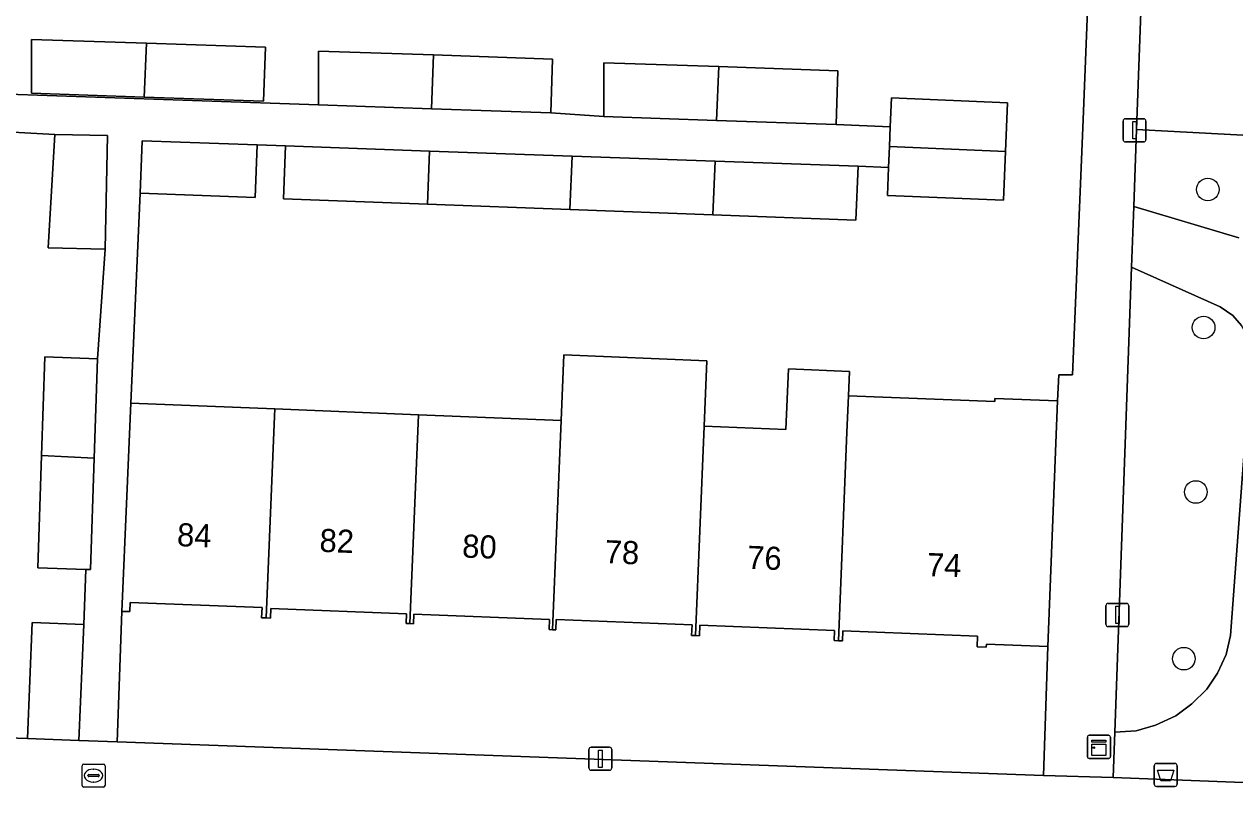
# Model space of a CAD drawing. Extents: x 161354 to 162026, y 386504 to 387460.
# Drawn here: x 161825.7 to 161878.1, y 386751.9 to 386785.2 of the extents above; entities that cross this region are included whole.
import ezdxf

# ---------------------------------------------------------------- set-up
doc = ezdxf.new("R2010")
doc.units = 0
for name, color, linetype in [('IMGEO_Afvalbak', 7, 'Continuous'), ('IMGEO_Boom', 7, 'Continuous'), ('IMGEO_Erf', 7, 'Continuous'), ('IMGEO_Groenvoorziening', 7, 'Continuous'), ('IMGEO_Kast', 7, 'Continuous'), ('IMGEO_Kolk', 7, 'Continuous'), ('IMGEO_Lichtmast', 7, 'Continuous'), ('IMGEO_Pand', 7, 'Continuous'), ('IMGEO_Pand_nummerreeks', 7, 'Continuous'), ('IMGEO_Voetpad_gesloten', 7, 'Continuous'), ('IMGEO_Voetpad_open', 7, 'Continuous')]:
    doc.layers.add(name, color=color, linetype=linetype)

msp = doc.modelspace()

# ---------------------------------------------------------------- linework, layer by layer
at = {"layer": 'IMGEO_Afvalbak'}
for p, q in [((161874.64, 386752.314), (161874.64, 386753.114)), ((161874.64, 386753.114), (161874.64, 386752.314)), ((161874.74, 386753.214), (161875.53, 386753.214)), ((161875.53, 386753.214), (161874.74, 386753.214)), ((161875.63, 386753.114), (161875.63, 386752.314)), ((161875.63, 386752.314), (161875.63, 386753.114)), ((161875.53, 386752.214), (161874.74, 386752.214)), ((161874.74, 386752.214), (161875.53, 386752.214))]:
    msp.add_line(p, q, dxfattribs=at)
msp.add_lwpolyline([(161874.783, 386752.928), (161875.487, 386752.928), (161875.338, 386752.458), (161874.932, 386752.458), (161874.783, 386752.928)], dxfattribs=at)
for centre, start, end in [((161874.74, 386753.114), 90, 180), ((161874.74, 386753.114), 90, 180), ((161875.53, 386753.114), 0, 90), ((161875.53, 386753.114), 360, 90), ((161874.74, 386752.314), 180, 270), ((161874.74, 386752.314), 180, 270), ((161875.53, 386752.314), 270, 0), ((161875.53, 386752.314), 270, 0)]:
    msp.add_arc(centre, 0.1, start, end, dxfattribs=at)
at = {"layer": 'IMGEO_Boom'}
for centre in [(161876.96, 386778.067), (161876.778, 386772.088), (161876.443, 386764.968), (161875.917, 386757.749)]:
    msp.add_circle(centre, 0.489, dxfattribs=at)
at = {"layer": 'IMGEO_Erf'}
for points in [[(161879.556, 386799.87), (161874.587, 386800.222), (161873.877, 386780.663), (161923.762, 386778.004)], [(161823.329, 386782.256), (161838.45, 386781.728), (161838.45, 386784.059), (161843.436, 386783.89), (161848.583, 386783.716), (161848.504, 386781.388), (161850.807, 386781.223), (161850.807, 386783.554), (161855.786, 386783.386), (161860.94, 386783.211), (161860.861, 386780.883), (161863.209, 386780.776), (161863.263, 386782.037), (161868.288, 386781.823), (161868.198, 386779.708), (161868.108, 386777.597), (161863.083, 386777.811), (161863.134, 386779.012), (161861.817, 386779.071), (161861.714, 386776.736), (161855.525, 386776.969), (161849.334, 386777.202), (161843.163, 386777.434), (161836.927, 386777.668), (161837.021, 386779.952), (161835.792, 386779.996), (161835.711, 386777.714), (161830.726, 386777.902), (161830.322, 386768.815), (161836.553, 386768.564), (161842.777, 386768.313), (161848.958, 386768.064), (161849.073, 386770.901), (161855.271, 386770.644), (161855.154, 386767.814), (161858.692, 386767.671), (161858.801, 386770.299), (161861.444, 386770.19), (161861.4, 386769.136), (161867.734, 386768.886), (161867.74, 386769.022), (161870.449, 386768.915), (161870.503, 386770.041), (161871.106, 386770.041), (161871.542, 386780.734), (161871.928, 386790.211)]]:
    msp.add_lwpolyline(points, dxfattribs=at)
for points in [[(161836.148, 386784.225), (161836.069, 386781.897), (161830.905, 386782.071), (161826.015, 386782.237), (161826.015, 386784.568), (161831.006, 386784.399)], [(161826.454, 386766.547), (161826.594, 386770.813), (161828.875, 386770.738), (161829.214, 386775.488), (161826.737, 386775.537), (161827.029, 386780.443), (161818.183, 386780.932), (161818.138, 386779.724), (161818.317, 386779.717), (161818.073, 386773.284), (161819.671, 386773.197), (161819.434, 386766.94), (161817.834, 386766.996), (161817.607, 386761.012), (161817.399, 386761.029), (161817.391, 386760.883), (161820.524, 386760.72), (161820.199, 386754.483), (161825.842, 386754.299), (161826.048, 386759.315), (161828.283, 386759.223), (161828.369, 386761.615), (161826.294, 386761.683)], [(161870.028, 386758.279), (161867.373, 386758.384), (161867.367, 386758.244), (161866.967, 386758.26), (161866.985, 386758.722), (161861.159, 386758.953), (161861.142, 386758.516), (161860.96, 386758.523), (161860.782, 386758.53), (161860.799, 386758.969), (161854.969, 386759.2), (161854.951, 386758.739), (161854.778, 386758.746), (161854.606, 386758.752), (161854.624, 386759.215), (161848.748, 386759.448), (161848.73, 386758.996), (161848.582, 386759.002), (161848.435, 386759.008), (161848.453, 386759.448), (161842.581, 386759.68), (161842.564, 386759.263), (161842.402, 386759.269), (161842.239, 386759.276), (161842.255, 386759.69), (161836.389, 386759.922), (161836.372, 386759.509), (161836.178, 386759.517), (161835.987, 386759.524), (161836.004, 386759.959), (161830.296, 386760.185), (161830.28, 386759.789), (161829.933, 386759.795), (161829.735, 386754.147), (161869.843, 386752.696)]]:
    msp.add_lwpolyline(points, close=True, dxfattribs=at)
at = {"layer": 'IMGEO_Groenvoorziening'}
for points in [[(161923.762, 386778.004), (161873.877, 386780.663), (161873.757, 386777.335), (161878.306, 386775.969)], [(161878.306, 386775.969), (161873.757, 386777.335), (161873.662, 386774.698), (161877.497, 386772.981), (161878.041, 386772.614), (161878.419, 386772.175)], [(161878.846, 386770.985), (161877.946, 386758.754), (161877.758, 386757.934), (161877.38, 386757.124), (161876.921, 386756.422), (161876.274, 386755.788), (161875.572, 386755.274), (161874.695, 386754.87), (161873.858, 386754.626), (161872.933, 386754.57), (161872.862, 386752.607), (161878.487, 386752.39)]]:
    msp.add_lwpolyline(points, dxfattribs=at)
msp.add_lwpolyline([(161872.933, 386754.57), (161873.858, 386754.626), (161874.695, 386754.87), (161875.572, 386755.274), (161876.274, 386755.788), (161876.921, 386756.422), (161877.38, 386757.124), (161877.758, 386757.934), (161877.946, 386758.754), (161878.846, 386770.985), (161878.729, 386771.595), (161878.419, 386772.175), (161878.041, 386772.614), (161877.497, 386772.981), (161873.662, 386774.698)], close=True, dxfattribs=at)
at = {"layer": 'IMGEO_Kast'}
for p, q in [((161871.743, 386753.505), (161871.743, 386754.346)), ((161871.743, 386754.346), (161871.743, 386753.505)), ((161871.818, 386754.43), (161872.659, 386754.43)), ((161872.659, 386754.43), (161871.818, 386754.43)), ((161872.743, 386754.355), (161872.743, 386753.514)), ((161872.743, 386753.514), (161872.743, 386754.355)), ((161872.668, 386753.43), (161871.827, 386753.43)), ((161871.827, 386753.43), (161872.668, 386753.43))]:
    msp.add_line(p, q, dxfattribs=at)
for points in [[(161871.938, 386754.22), (161872.538, 386754.22), (161872.538, 386754.135), (161871.938, 386754.135), (161871.938, 386754.22)], [(161871.938, 386754.045), (161872.538, 386754.045), (161872.538, 386753.556), (161871.938, 386753.556), (161871.938, 386754.045)]]:
    msp.add_lwpolyline(points, dxfattribs=at)
msp.add_circle((161872.022, 386753.894), 0.0377, dxfattribs=at)
for centre, start, end in [((161871.821, 386754.352), 92.4484, 184.2845), ((161871.821, 386754.352), 92.4484, 184.2845), ((161872.665, 386754.352), 2.4484, 94.2845), ((161872.665, 386754.352), 2.4484, 94.2845), ((161871.821, 386753.508), 182.4484, 274.2845), ((161871.821, 386753.508), 182.4484, 274.2845), ((161872.665, 386753.508), 272.4484, 4.2845), ((161872.665, 386753.508), 272.4484, 4.2845)]:
    msp.add_arc(centre, 0.0779, start, end, dxfattribs=at)
at = {"layer": 'IMGEO_Kolk'}
for p, q in [((161828.209, 386752.26), (161828.209, 386753.112)), ((161828.284, 386753.186), (161829.136, 386753.186)), ((161829.21, 386753.112), (161829.21, 386752.26)), ((161828.468, 386752.68), (161828.468, 386752.692)), ((161828.906, 386752.643), (161828.508, 386752.643)), ((161828.511, 386752.729), (161828.909, 386752.729)), ((161828.697, 386752.966), (161828.722, 386752.966)), ((161828.952, 386752.692), (161828.952, 386752.68)), ((161829.136, 386752.186), (161828.284, 386752.186)), ((161828.72, 386752.406), (161828.695, 386752.406))]:
    msp.add_line(p, q, dxfattribs=at)
for points in [[(161828.209, 386752.26), (161828.209, 386753.112)], [(161828.284, 386753.186), (161829.136, 386753.186)], [(161829.21, 386753.112), (161829.21, 386752.26)], [(161829.136, 386752.186), (161828.284, 386752.186)]]:
    msp.add_lwpolyline(points, dxfattribs=at)
for centre, radius, start, end in [((161828.286, 386753.11), 0.0765, 91.552, 178.448), ((161828.286, 386753.11), 0.0765, 91.552, 178.448), ((161829.134, 386753.11), 0.0765, 1.552, 88.448), ((161829.134, 386753.11), 0.0765, 1.552, 88.448), ((161828.508, 386752.689), 0.0403, 85.8775, 175.7526), ((161828.505, 386752.679), 0.0366, 178.938, 274.7102), ((161828.909, 386752.686), 0.043, 264.8664, 352.4533), ((161828.913, 386752.691), 0.0386, 1.7309, 96.639), ((161828.286, 386752.262), 0.0765, 181.552, 268.448), ((161828.286, 386752.262), 0.0765, 181.552, 268.448), ((161829.134, 386752.262), 0.0765, 271.552, 358.448), ((161829.134, 386752.262), 0.0765, 271.552, 358.448)]:
    msp.add_arc(centre, radius, start, end, dxfattribs=at)
for centre, major_axis, ratio, start_param, end_param in [((161828.696, 386752.686), (-0.387, 0.002), 0.722429, 4.712389, 7.853982), ((161828.721, 386752.686), (-0.39, 0.002), 0.717154, 1.570796, 4.712389)]:
    msp.add_ellipse(centre, major_axis=major_axis, ratio=ratio, start_param=start_param, end_param=end_param, dxfattribs=at)
at = {"layer": 'IMGEO_Lichtmast'}
for p, q in [((161873.292, 386780.228), (161873.292, 386781.028)), ((161873.292, 386781.028), (161873.292, 386780.228)), ((161873.392, 386781.128), (161874.182, 386781.128)), ((161874.182, 386781.128), (161873.392, 386781.128)), ((161874.282, 386781.028), (161874.282, 386780.228)), ((161874.282, 386780.228), (161874.282, 386781.028)), ((161874.182, 386780.128), (161873.392, 386780.128)), ((161873.392, 386780.128), (161874.182, 386780.128)), ((161872.55, 386759.241), (161872.55, 386760.041)), ((161872.55, 386760.041), (161872.55, 386759.241)), ((161872.65, 386760.141), (161873.44, 386760.141)), ((161873.44, 386760.141), (161872.65, 386760.141)), ((161873.54, 386760.041), (161873.54, 386759.241)), ((161873.54, 386759.241), (161873.54, 386760.041)), ((161873.44, 386759.141), (161872.65, 386759.141)), ((161872.65, 386759.141), (161873.44, 386759.141)), ((161850.161, 386753.018), (161850.161, 386753.818)), ((161850.161, 386753.818), (161850.161, 386753.018)), ((161850.261, 386753.918), (161851.051, 386753.918)), ((161851.051, 386753.918), (161850.261, 386753.918)), ((161851.151, 386753.818), (161851.151, 386753.018)), ((161851.151, 386753.018), (161851.151, 386753.818)), ((161851.051, 386752.918), (161850.261, 386752.918)), ((161850.261, 386752.918), (161851.051, 386752.918))]:
    msp.add_line(p, q, dxfattribs=at)
for points in [[(161873.712, 386781.003), (161873.862, 386781.003), (161873.862, 386780.253), (161873.712, 386780.253), (161873.712, 386781.003)], [(161872.97, 386760.016), (161873.12, 386760.016), (161873.12, 386759.266), (161872.97, 386759.266), (161872.97, 386760.016)], [(161850.581, 386753.793), (161850.731, 386753.793), (161850.731, 386753.043), (161850.581, 386753.043), (161850.581, 386753.793)]]:
    msp.add_lwpolyline(points, dxfattribs=at)
for centre, start, end in [((161873.392, 386781.028), 90, 180), ((161873.392, 386781.028), 90, 180), ((161874.182, 386781.028), 0, 90), ((161874.182, 386781.028), 360, 90), ((161873.392, 386780.228), 180, 270), ((161873.392, 386780.228), 180, 270), ((161874.182, 386780.228), 270, 0), ((161874.182, 386780.228), 270, 0), ((161872.65, 386760.041), 90, 180), ((161872.65, 386760.041), 90, 180), ((161873.44, 386760.041), 0, 90), ((161873.44, 386760.041), 360, 90), ((161872.65, 386759.241), 180, 270), ((161872.65, 386759.241), 180, 270), ((161873.44, 386759.241), 270, 0), ((161873.44, 386759.241), 270, 0), ((161850.261, 386753.818), 90, 180), ((161850.261, 386753.818), 90, 180), ((161851.051, 386753.818), 0, 90), ((161851.051, 386753.818), 360, 90), ((161850.261, 386753.018), 180, 270), ((161850.261, 386753.018), 180, 270), ((161851.051, 386753.018), 270, 0), ((161851.051, 386753.018), 270, 0)]:
    msp.add_arc(centre, 0.1, start, end, dxfattribs=at)
at = {"layer": 'IMGEO_Pand'}
for points in [[(161826.015, 386784.568), (161826.015, 386782.237), (161830.905, 386782.071), (161831.006, 386784.399)], [(161836.069, 386781.897), (161836.148, 386784.225), (161831.006, 386784.399), (161830.905, 386782.071)], [(161838.45, 386784.059), (161838.45, 386781.728), (161843.337, 386781.562), (161843.436, 386783.89)], [(161848.504, 386781.388), (161848.583, 386783.716), (161843.436, 386783.89), (161843.337, 386781.562)], [(161850.807, 386783.554), (161850.807, 386781.223), (161855.691, 386781.057), (161855.786, 386783.386)], [(161860.861, 386780.883), (161860.94, 386783.211), (161855.786, 386783.386), (161855.691, 386781.057)], [(161868.288, 386781.823), (161863.263, 386782.037), (161863.209, 386780.776), (161863.173, 386779.922), (161868.198, 386779.708)], [(161829.311, 386780.398), (161827.029, 386780.443), (161826.737, 386775.537), (161829.214, 386775.488)], [(161835.792, 386779.996), (161830.811, 386780.172), (161830.726, 386777.902), (161835.711, 386777.714)], [(161843.26, 386779.73), (161837.021, 386779.952), (161836.927, 386777.668), (161843.163, 386777.434)], [(161868.198, 386779.708), (161863.173, 386779.922), (161863.134, 386779.012), (161863.083, 386777.811), (161868.108, 386777.597)], [(161849.429, 386779.511), (161843.26, 386779.73), (161843.163, 386777.434), (161849.334, 386777.202)], [(161855.62, 386779.291), (161849.429, 386779.511), (161849.334, 386777.202), (161855.525, 386776.969)], [(161855.525, 386776.969), (161861.714, 386776.736), (161861.817, 386779.071), (161855.62, 386779.291)], [(161855.271, 386770.644), (161849.073, 386770.901), (161848.958, 386768.064), (161848.582, 386759.002), (161848.73, 386758.996), (161848.748, 386759.448), (161854.624, 386759.215), (161854.606, 386758.752), (161854.778, 386758.746), (161855.154, 386767.814)], [(161828.875, 386770.738), (161826.594, 386770.813), (161826.454, 386766.547), (161828.734, 386766.428)], [(161861.335, 386767.564), (161861.4, 386769.136), (161861.444, 386770.19), (161858.801, 386770.299), (161858.692, 386767.671), (161855.154, 386767.814), (161854.778, 386758.746), (161854.951, 386758.739), (161854.969, 386759.2), (161860.799, 386758.969), (161860.782, 386758.53), (161860.96, 386758.523)], [(161836.54, 386768.248), (161836.553, 386768.564), (161830.322, 386768.815), (161830.148, 386764.791), (161829.933, 386759.795), (161830.28, 386759.789), (161830.296, 386760.185), (161836.004, 386759.959), (161835.987, 386759.524), (161836.178, 386759.517)], [(161870.449, 386768.915), (161867.74, 386769.022), (161867.734, 386768.886), (161861.4, 386769.136), (161861.335, 386767.564), (161860.96, 386758.523), (161861.142, 386758.516), (161861.159, 386758.953), (161866.985, 386758.722), (161866.967, 386758.26), (161867.367, 386758.244), (161867.373, 386758.384), (161870.028, 386758.279)], [(161836.178, 386759.517), (161836.372, 386759.509), (161836.389, 386759.922), (161842.255, 386759.69), (161842.239, 386759.276), (161842.402, 386759.269), (161842.777, 386768.313), (161836.553, 386768.564), (161836.54, 386768.248)], [(161842.402, 386759.269), (161842.564, 386759.263), (161842.581, 386759.68), (161848.453, 386759.448), (161848.435, 386759.008), (161848.582, 386759.002), (161848.958, 386768.064), (161842.777, 386768.313)], [(161828.734, 386766.428), (161826.454, 386766.547), (161826.294, 386761.683), (161828.369, 386761.615), (161828.575, 386761.608)], [(161828.077, 386754.207), (161828.283, 386759.223), (161826.048, 386759.315), (161825.842, 386754.299)]]:
    msp.add_lwpolyline(points, close=True, dxfattribs=at)
at = {"layer": 'IMGEO_Voetpad_gesloten'}
msp.add_lwpolyline([(161818.183, 386780.932), (161827.029, 386780.443), (161829.311, 386780.398), (161829.214, 386775.488), (161828.875, 386770.738), (161828.734, 386766.428), (161828.575, 386761.608), (161828.369, 386761.615), (161828.283, 386759.223), (161828.077, 386754.207), (161829.735, 386754.147), (161829.933, 386759.795), (161830.148, 386764.791), (161830.322, 386768.815), (161830.726, 386777.902), (161830.811, 386780.172), (161835.792, 386779.996), (161837.021, 386779.952), (161843.26, 386779.73), (161849.429, 386779.511), (161855.62, 386779.291), (161861.817, 386779.071), (161863.134, 386779.012), (161863.173, 386779.922), (161863.209, 386780.776), (161860.861, 386780.883), (161855.691, 386781.057), (161850.807, 386781.223), (161848.504, 386781.388), (161843.337, 386781.562), (161838.45, 386781.728), (161823.329, 386782.256)], dxfattribs=at)
at = {"layer": 'IMGEO_Voetpad_open'}
msp.add_lwpolyline([(161874.587, 386800.222), (161874.747, 386804.628), (161871.979, 386804.738), (161871.684, 386798.765), (161871.679, 386798.614), (161871.431, 386791.311), (161871.381, 386790.22), (161871.928, 386790.211), (161871.542, 386780.734), (161871.106, 386770.041), (161870.503, 386770.041), (161870.449, 386768.915), (161870.028, 386758.279), (161869.843, 386752.696), (161872.862, 386752.607), (161872.933, 386754.57), (161873.662, 386774.698), (161873.757, 386777.335), (161873.877, 386780.663)], close=True, dxfattribs=at)
msp.add_lwpolyline([(161878.487, 386752.39), (161872.862, 386752.607), (161869.843, 386752.696), (161829.735, 386754.147), (161828.077, 386754.207), (161825.842, 386754.299), (161820.199, 386754.483), (161817.064, 386754.602), (161816.207, 386754.635), (161809.386, 386754.894), (161809.266, 386751.829)], dxfattribs=at)

# ---------------------------------------------------------------- texts
at = {"layer": 'IMGEO_Pand_nummerreeks'}
for s, rotation, p in [('84', 357.7166, (161832.311, 386762.626)), ('82', 357.7166, (161838.481, 386762.38)), ('80', 357.7166, (161844.659, 386762.134)), ('78', 357.7166, (161850.831, 386761.888)), ('76', 357.7139, (161857, 386761.643)), ('74', 357.7311, (161864.784, 386761.331))]:
    msp.add_text(s, height=1, rotation=rotation, dxfattribs=at).set_placement(p)

doc.saveas('drawing.dxf')
